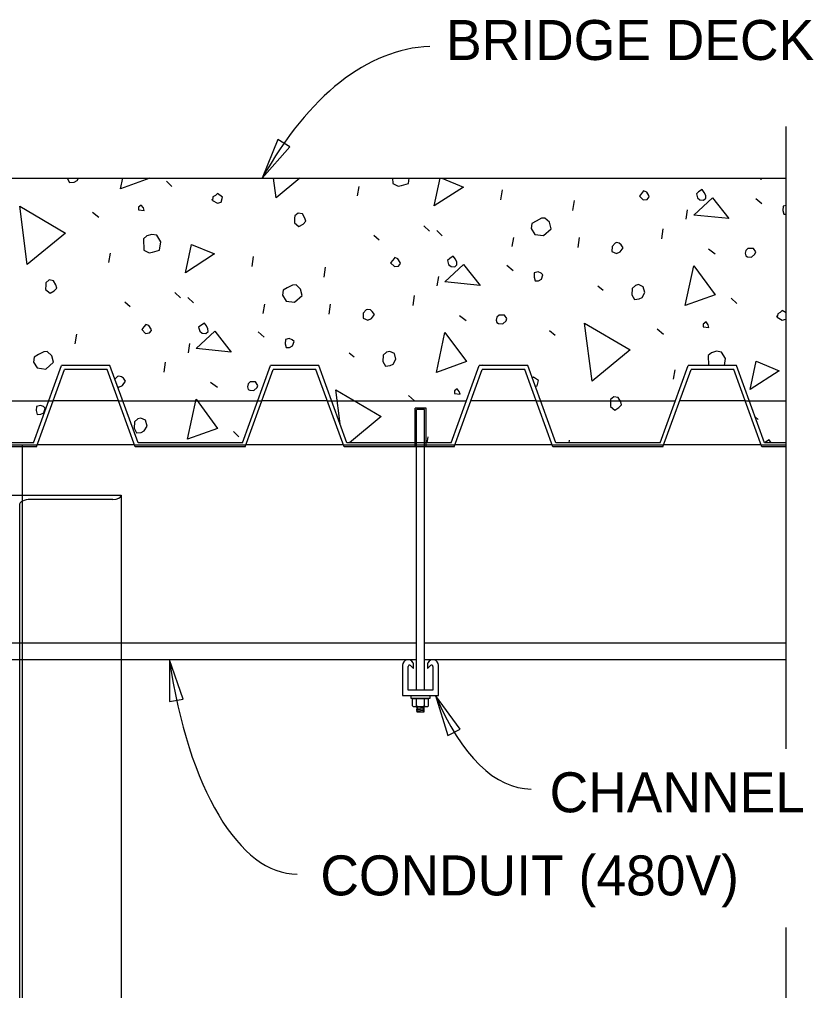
# Model space of a CAD drawing. Extents: x 927736.2 to 927809.6, y 636703.6 to 636757.7.
# Drawn here: x 927796.47 to 927803.88, y 636748.62 to 636757.67 of the extents above; entities that cross this region are included whole.
import ezdxf

# ---------------------------------------------------------------- set-up
doc = ezdxf.new("R2010")
doc.units = 0
for name, color, linetype in [('DimLines_dp', 7, 'Continuous'), ('Miscellaneous1', 7, 'Continuous'), ('Miscellaneous2', 7, 'Continuous'), ('Miscellaneous3', 7, 'Continuous')]:
    doc.layers.add(name, color=color, linetype=linetype)

msp = doc.modelspace()

# ---------------------------------------------------------------- linework, layer by layer
at = {"layer": 'DimLines_dp'}
for points in [[(927803.6221, 636750.8704), (927803.6221, 636756.6765)], [(927803.6221, 636737.7816), (927803.6221, 636747.0555), (927803.431, 636747.0555), (927803.6221, 636747.1387), (927803.8133, 636747.222), (927803.6221, 636747.222), (927803.6221, 636749.2035)]]:
    msp.add_lwpolyline(points, dxfattribs=at)
for points in [[(927798.7324, 636756.1928), (927798.9906, 636756.4861), (927798.8795, 636756.5548)], [(927797.8655, 636751.702), (927797.8657, 636751.3112), (927797.9944, 636751.3331)], [(927800.3508, 636751.368), (927800.4651, 636750.9943), (927800.5818, 636751.0528)]]:
    msp.add_lwpolyline(points, close=True, dxfattribs=at)
for centre, major_axis, ratio, start_param, end_param in [((927800.5703, 636751.583), (0.2741, -5.8397), 0.464296, 3.141604, 3.781059), ((927799.0396, 636752.6162), (0.0188, -2.9139), 0.426092, 5.02876, 6.283138), ((927801.2258, 636753.4099), (0.0188, -2.9139), 0.426092, 5.486066, 6.283138)]:
    msp.add_ellipse(centre, major_axis=major_axis, ratio=ratio, start_param=start_param, end_param=end_param, dxfattribs=at)
at = {"layer": 'Miscellaneous1'}
for p, q in [((927797.4166, 636751.8562), (927795.952, 636751.8562)), ((927800.1719, 636751.8562), (927797.4166, 636751.8562)), ((927803.6221, 636751.8562), (927800.2488, 636751.8562)), ((927797.4166, 636751.702), (927795.952, 636751.702)), ((927800.1719, 636751.702), (927797.4166, 636751.702)), ((927800.146, 636751.6626), (927800.1407, 636751.6733)), ((927800.146, 636751.6185), (927800.146, 636751.6626)), ((927803.6221, 636751.702), (927800.2488, 636751.702)), ((927800.28, 636751.6733), (927800.2747, 636751.6626)), ((927800.2747, 636751.6626), (927800.2747, 636751.6185)), ((927800.0434, 636751.6507), (927800.0434, 636751.368)), ((927800.0947, 636751.4193), (927800.0947, 636751.6388)), ((927800.1166, 636751.6479), (927800.146, 636751.6185)), ((927800.2747, 636751.6185), (927800.3041, 636751.6479)), ((927800.326, 636751.6388), (927800.326, 636751.4193)), ((927800.3773, 636751.368), (927800.3773, 636751.6507)), ((927800.326, 636751.4193), (927800.0947, 636751.4193)), ((927800.0434, 636751.368), (927800.3773, 636751.368))]:
    msp.add_line(p, q, dxfattribs=at)
for centre, radius, start, end in [((927800.0947, 636751.6507), 0.0513, 26.17936, 179.9999), ((927800.326, 636751.6507), 0.0513, 0.0001, 153.82064), ((927800.1075, 636751.6388), 0.0128, 45, 180), ((927800.3132, 636751.6388), 0.0128, 360, 135)]:
    msp.add_arc(centre, radius, start, end, dxfattribs=at)
at = {"layer": 'Miscellaneous2'}
for p, q in [((927786.3327, 636756.1929), (927803.6221, 636756.1929)), ((927803.3889, 636756.1769), (927803.3917, 636756.1929)), ((927797.838, 636756.1643), (927797.8897, 636756.1143)), ((927799.6233, 636756.0298), (927799.6383, 636756.1168)), ((927800.9613, 636755.9924), (927800.9746, 636756.0854)), ((927803.3395, 636756.004), (927803.3971, 636755.9556)), ((927801.6331, 636755.8915), (927801.6465, 636755.9845)), ((927797.1488, 636755.8774), (927797.2064, 636755.829)), ((927802.689, 636755.8106), (927802.704, 636755.8976)), ((927800.2414, 636755.7485), (927800.2931, 636755.6985)), ((927799.7731, 636755.6613), (927799.8232, 636755.6173)), ((927800.3618, 636755.7041), (927800.4135, 636755.6541)), ((927801.0658, 636755.5544), (927801.0808, 636755.6414)), ((927801.6808, 636755.5468), (927801.6942, 636755.6398)), ((927802.4632, 636755.6288), (927802.4766, 636755.7217)), ((927797.3003, 636755.4073), (927797.3153, 636755.4943)), ((927798.6382, 636755.37), (927798.6516, 636755.4629)), ((927802.8971, 636755.5344), (927802.9607, 636755.4876)), ((927801.0164, 636755.3816), (927801.0741, 636755.3332)), ((927799.31, 636755.2691), (927799.3234, 636755.362)), ((927800.366, 636755.1881), (927800.381, 636755.2751)), ((927801.8663, 636755.1879), (927801.9148, 636755.1499)), ((927797.9183, 636755.126), (927797.97, 636755.076)), ((927800.1402, 636755.0063), (927800.1536, 636755.0993)), ((927797.4501, 636755.0388), (927797.5002, 636754.9948)), ((927798.0387, 636755.0817), (927798.0904, 636755.0317)), ((927798.7428, 636754.9319), (927798.7578, 636755.019)), ((927799.3577, 636754.9243), (927799.3711, 636755.0173)), ((927803.1098, 636755.0742), (927803.1615, 636755.0242)), ((927800.5741, 636754.9119), (927800.6377, 636754.8651)), ((927796.987, 636754.6466), (927797.0004, 636754.7396)), ((927798.6934, 636754.7591), (927798.751, 636754.7107)), ((927801.4156, 636754.7735), (927801.4657, 636754.7294)), ((927802.4205, 636754.7874), (927802.4782, 636754.739)), ((927798.0429, 636754.5657), (927798.0579, 636754.6527)), ((927799.5433, 636754.5655), (927799.5918, 636754.5274)), ((927797.8171, 636754.3839), (927797.8305, 636754.4768)), ((927796.5973, 636753.7261), (927796.8593, 636754.4458)), ((927796.6243, 636753.6876), (927796.8862, 636754.4073)), ((927797.3114, 636754.4458), (927796.8593, 636754.4458)), ((927797.2845, 636754.4073), (927796.8862, 636754.4073)), ((927797.5464, 636753.6876), (927797.2845, 636754.4073)), ((927797.5733, 636753.7261), (927797.3114, 636754.4458)), ((927798.5471, 636753.7261), (927798.809, 636754.4458)), ((927798.574, 636753.6876), (927798.836, 636754.4073)), ((927799.2612, 636754.4458), (927798.809, 636754.4458)), ((927799.2342, 636754.4073), (927798.836, 636754.4073)), ((927799.4962, 636753.6876), (927799.2342, 636754.4073)), ((927799.5231, 636753.7261), (927799.2612, 636754.4458)), ((927800.4968, 636753.7261), (927800.7588, 636754.4458)), ((927800.5238, 636753.6876), (927800.7857, 636754.4073)), ((927801.2109, 636754.4458), (927800.7588, 636754.4458)), ((927801.184, 636754.4073), (927800.7857, 636754.4073)), ((927800.7867, 636754.4518), (927800.7929, 636754.4458)), ((927801.4459, 636753.6876), (927801.184, 636754.4073)), ((927801.4728, 636753.7261), (927801.2109, 636754.4458)), ((927802.4466, 636753.7261), (927802.7085, 636754.4458)), ((927802.4735, 636753.6876), (927802.7355, 636754.4073)), ((927802.572, 636754.3173), (927802.587, 636754.4043)), ((927803.1607, 636754.4458), (927802.7085, 636754.4458)), ((927803.1337, 636754.4073), (927802.7355, 636754.4073)), ((927803.3957, 636753.6876), (927803.1337, 636754.4073)), ((927803.4226, 636753.7261), (927803.1607, 636754.4458)), ((927798.251, 636754.2894), (927798.3146, 636754.2426)), ((927800.0975, 636754.1649), (927800.1551, 636754.1165)), ((927800.2617, 636754.0473), (927800.159, 636754.0473)), ((927800.159, 636753.6876), (927800.159, 636754.0473)), ((927800.2488, 636754.0344), (927800.1719, 636754.0344)), ((927800.2617, 636753.6876), (927800.2617, 636754.0473)), ((927803.3344, 636753.9685), (927803.3622, 636753.9416)), ((927798.4637, 636753.8293), (927798.5154, 636753.7793)), ((927800.2715, 636753.7261), (927800.2811, 636753.7818)), ((927801.5968, 636753.7261), (927801.6003, 636753.7504)), ((927796.6243, 636753.6876), (927795.5967, 636753.6876)), ((927796.5973, 636753.7261), (927795.6236, 636753.7261)), ((927798.574, 636753.6876), (927797.5464, 636753.6876)), ((927798.5471, 636753.7261), (927797.5733, 636753.7261)), ((927799.4893, 636753.7065), (927799.6693, 636753.7065)), ((927800.5238, 636753.6876), (927799.4962, 636753.6876)), ((927800.4968, 636753.7261), (927799.5231, 636753.7261)), ((927801.439, 636753.7065), (927801.619, 636753.7065)), ((927802.4735, 636753.6876), (927801.4459, 636753.6876)), ((927802.4466, 636753.7261), (927801.4728, 636753.7261)), ((927803.3888, 636753.7065), (927803.5688, 636753.7065)), ((927803.6221, 636753.6876), (927803.3957, 636753.6876)), ((927803.6221, 636753.7261), (927803.4226, 636753.7261))]:
    msp.add_line(p, q, dxfattribs=at)
for points in [[(927796.912, 636756.1929), (927796.9347, 636756.1521), (927796.978, 636756.1573), (927797.0062, 636756.1712), (927797.0188, 636756.1929)], [(927797.4099, 636756.0942), (927797.4308, 636756.1929)], [(927797.6846, 636756.1929), (927797.4099, 636756.0942)], [(927798.8623, 636756.011), (927798.8392, 636756.1929)], [(927799.083, 636756.1929), (927798.8623, 636756.011)], [(927799.949, 636756.1929), (927799.9505, 636756.143), (927800.0018, 636756.1184), (927800.0316, 636756.1264), (927800.0971, 636756.1439), (927800.1037, 636756.1929)], [(927800.3385, 636755.9341), (927800.3942, 636756.1929)], [(927800.4083, 636756.1929), (927800.6108, 636756.1092), (927800.3385, 636755.9341)], [(927798.2688, 636755.986), (927798.3141, 636755.9599), (927798.3499, 636755.9694), (927798.3625, 636756.0175), (927798.3156, 636756.0496), (927798.295, 636756.0313), (927798.2728, 636756.019), (927798.2688, 636755.986), (927798.2656, 636755.9979)], [(927802.2546, 636756.0262), (927802.2896, 636755.9908), (927802.3269, 636755.9945), (927802.346, 636756.0187), (927802.3428, 636756.0306), (927802.3213, 636756.0632), (927802.2927, 636756.0747), (927802.2736, 636756.0504), (927802.2546, 636756.0262)], [(927802.7617, 636755.8492), (927802.9355, 636756.0107), (927803.0898, 636755.8158), (927802.7617, 636755.8492)], [(927802.7948, 636756.0113), (927802.8191, 636755.9923), (927802.8521, 636755.9883), (927802.8727, 636756.0066), (927802.8723, 636756.0321), (927802.8583, 636756.0602), (927802.8384, 636756.0868), (927802.8059, 636756.0653), (927802.7853, 636756.047), (927802.7948, 636756.0113)], [(927796.5392, 636755.3885), (927796.4702, 636755.9318), (927796.8948, 636755.6817), (927796.5392, 636755.3885)], [(927797.5778, 636755.8966), (927797.6302, 636755.8915), (927797.6238, 636755.9153), (927797.6039, 636755.9419), (927797.5773, 636755.922), (927797.5778, 636755.8966)], [(927803.6221, 636755.9393), (927803.595, 636755.932), (927803.5926, 636755.8931)], [(927799.0345, 636755.8209), (927799.0338, 636755.776), (927799.0747, 636755.7423), (927799.1132, 636755.7654), (927799.1382, 636755.7912), (927799.1302, 636755.821), (927799.1071, 636755.8595), (927799.0666, 636755.8678), (927799.0357, 636755.8404), (927799.0345, 636755.8209)], [(927801.244, 636755.7234), (927801.2778, 636755.6687), (927801.3573, 636755.658), (927801.4295, 636755.7221), (927801.4136, 636755.7816), (927801.371, 636755.8213), (927801.3396, 636755.8193), (927801.2892, 636755.793), (927801.2507, 636755.7699), (927801.244, 636755.7234)], [(927803.5926, 636755.8931), (927803.6022, 636755.8574), (927803.6221, 636755.8586)], [(927797.6242, 636755.6281), (927797.6275, 636755.5205), (927797.6787, 636755.4959), (927797.7085, 636755.5039), (927797.774, 636755.5215), (927797.7847, 636755.6009), (927797.7492, 636755.6617), (927797.7028, 636755.6684), (927797.6551, 636755.6556), (927797.6242, 636755.6281)], [(927798.0154, 636755.3116), (927798.0723, 636755.5759), (927798.2877, 636755.4867), (927798.0154, 636755.3116)], [(927801.9978, 636755.5551), (927801.997, 636755.5102), (927802.0407, 636755.49), (927802.0749, 636755.5056), (927802.1026, 636755.5449), (927802.0827, 636755.5715), (927802.066, 636755.5862), (927802.039, 636755.5917), (927802.0271, 636755.5885), (927801.9978, 636755.5551)], [(927800.4718, 636755.3888), (927800.496, 636755.3698), (927800.529, 636755.3659), (927800.5497, 636755.3842), (927800.5492, 636755.4096), (927800.5353, 636755.4378), (927800.5154, 636755.4644), (927800.4828, 636755.4429), (927800.4622, 636755.4246), (927800.4718, 636755.3888)], [(927803.2467, 636755.4684), (927803.2619, 636755.4597), (927803.3008, 636755.4574), (927803.3317, 636755.4848), (927803.3389, 636755.5059), (927803.3174, 636755.5384), (927803.2665, 636755.5376), (927803.2459, 636755.5193), (927803.2404, 636755.4923), (927803.2467, 636755.4684)], [(927799.9315, 636755.4037), (927799.9665, 636755.3684), (927800.0039, 636755.372), (927800.0229, 636755.3963), (927800.0197, 636755.4082), (927799.9982, 636755.4407), (927799.9696, 636755.4522), (927799.9506, 636755.4279), (927799.9315, 636755.4037)], [(927800.4386, 636755.2267), (927800.6124, 636755.3882), (927800.7668, 636755.1934), (927800.4386, 636755.2267)], [(927802.6816, 636755.0042), (927802.7606, 636755.3765), (927802.9612, 636755.1046), (927802.6816, 636755.0042)], [(927801.2696, 636755.2706), (927801.2791, 636755.2349), (927801.3105, 636755.2369), (927801.3387, 636755.2509), (927801.353, 636755.293), (927801.3363, 636755.3077), (927801.3076, 636755.3191), (927801.2719, 636755.3096), (927801.2696, 636755.2706)], [(927796.7114, 636755.1984), (927796.7107, 636755.1536), (927796.7517, 636755.1198), (927796.7902, 636755.1429), (927796.8152, 636755.1688), (927796.8072, 636755.1986), (927796.7841, 636755.2371), (927796.7436, 636755.2454), (927796.7126, 636755.2179), (927796.7114, 636755.1984)], [(927798.921, 636755.101), (927798.9548, 636755.0462), (927799.0342, 636755.0356), (927799.1065, 636755.0996), (927799.0905, 636755.1592), (927799.0479, 636755.1989), (927799.0166, 636755.1968), (927798.9662, 636755.1706), (927798.9276, 636755.1475), (927798.921, 636755.101)], [(927802.1853, 636755.1649), (927802.1818, 636755.1065), (927802.2065, 636755.062), (927802.2498, 636755.0672), (927802.278, 636755.0812), (927802.3041, 636755.1265), (927802.2898, 636755.1801), (927802.246, 636755.2003), (927802.2163, 636755.1923), (927802.1853, 636755.1649)], [(927799.6747, 636754.9327), (927799.674, 636754.8878), (927799.7177, 636754.8676), (927799.7518, 636754.8831), (927799.7796, 636754.9225), (927799.7597, 636754.9491), (927799.743, 636754.9637), (927799.716, 636754.9693), (927799.7041, 636754.9661), (927799.6747, 636754.9327)], [(927800.9237, 636754.846), (927800.9388, 636754.8373), (927800.9777, 636754.8349), (927801.0087, 636754.8624), (927801.0158, 636754.8834), (927800.9943, 636754.916), (927800.9435, 636754.9151), (927800.9228, 636754.8968), (927800.9173, 636754.8698), (927800.9237, 636754.846)], [(927803.6221, 636754.9358), (927803.5874, 636754.9596), (927803.5668, 636754.9413), (927803.5445, 636754.929), (927803.5406, 636754.896), (927803.5374, 636754.9079)], [(927797.6085, 636754.7812), (927797.6435, 636754.7459), (927797.6808, 636754.7495), (927797.6999, 636754.7738), (927797.6967, 636754.7857), (927797.6752, 636754.8183), (927797.6466, 636754.8297), (927797.6275, 636754.8055), (927797.6085, 636754.7812)], [(927798.1487, 636754.7664), (927798.173, 636754.7473), (927798.206, 636754.7434), (927798.2266, 636754.7617), (927798.2262, 636754.7871), (927798.2122, 636754.8153), (927798.1923, 636754.8419), (927798.1598, 636754.8204), (927798.1392, 636754.8021), (927798.1487, 636754.7664)], [(927801.811, 636754.2985), (927801.742, 636754.8418), (927802.1665, 636754.5916), (927801.811, 636754.2985)], [(927802.8495, 636754.8066), (927802.902, 636754.8015), (927802.8956, 636754.8253), (927802.8757, 636754.8519), (927802.8491, 636754.832), (927802.8495, 636754.8066)], [(927803.5406, 636754.896), (927803.5859, 636754.8698), (927803.6216, 636754.8794), (927803.6221, 636754.8811)], [(927798.1156, 636754.6043), (927798.2894, 636754.7658), (927798.4437, 636754.5709), (927798.1156, 636754.6043)], [(927800.3586, 636754.3817), (927800.4376, 636754.754), (927800.6381, 636754.4822), (927800.3586, 636754.3817)], [(927798.9465, 636754.6482), (927798.9561, 636754.6124), (927798.9875, 636754.6145), (927799.0157, 636754.6284), (927799.0299, 636754.6705), (927799.0132, 636754.6852), (927798.9846, 636754.6967), (927798.9489, 636754.6871), (927798.9465, 636754.6482)], [(927796.5979, 636754.4785), (927796.6317, 636754.4237), (927796.7112, 636754.4131), (927796.7834, 636754.4772), (927796.7674, 636754.5367), (927796.7249, 636754.5764), (927796.6935, 636754.5744), (927796.6431, 636754.5481), (927796.6046, 636754.525), (927796.5979, 636754.4785)], [(927799.8623, 636754.5424), (927799.8588, 636754.484), (927799.8834, 636754.4396), (927799.9267, 636754.4448), (927799.9549, 636754.4587), (927799.9811, 636754.504), (927799.9667, 636754.5576), (927799.923, 636754.5778), (927799.8932, 636754.5699), (927799.8623, 636754.5424)], [(927803.0477, 636754.4458), (927803.0564, 636754.5109), (927803.021, 636754.5716), (927802.9745, 636754.5783), (927802.9269, 636754.5655), (927802.8959, 636754.5381)], [(927802.8959, 636754.5381), (927802.8987, 636754.4458)], [(927803.2872, 636754.2216), (927803.3441, 636754.4858), (927803.5595, 636754.3967), (927803.2872, 636754.2216)], [(927797.3824, 636754.2508), (927797.3946, 636754.2451), (927797.4288, 636754.2606), (927797.4565, 636754.3), (927797.4366, 636754.3266), (927797.4199, 636754.3413), (927797.3929, 636754.3468), (927797.381, 636754.3436), (927797.3581, 636754.3175)], [(927798.6006, 636754.2235), (927798.6157, 636754.2148), (927798.6547, 636754.2125), (927798.6856, 636754.2399), (927798.6928, 636754.261), (927798.6713, 636754.2935), (927798.6204, 636754.2927), (927798.5998, 636754.2744), (927798.5943, 636754.2473), (927798.6006, 636754.2235)], [(927801.2813, 636754.2523), (927801.2986, 636754.2569), (927801.3112, 636754.305), (927801.2643, 636754.3371), (927801.2538, 636754.3278)], [(927799.4593, 636753.9014), (927799.4189, 636754.2193), (927799.8435, 636753.9692), (927799.5487, 636753.7261)], [(927800.5265, 636754.1841), (927800.5789, 636754.179), (927800.5725, 636754.2028), (927800.5526, 636754.2294), (927800.526, 636754.2095), (927800.5265, 636754.1841)], [(927798.0355, 636753.7593), (927798.1145, 636754.1316), (927798.3151, 636753.8597), (927798.0355, 636753.7593)], [(927801.9832, 636754.1084), (927801.9825, 636754.0635), (927802.0234, 636754.0298), (927802.0619, 636754.0529), (927802.0869, 636754.0787), (927802.0789, 636754.1085), (927802.0558, 636754.147), (927802.0153, 636754.1553), (927801.9844, 636754.1279), (927801.9832, 636754.1084)], [(927796.6235, 636754.0257), (927796.633, 636753.99), (927796.6644, 636753.992), (927796.6926, 636754.0059), (927796.7069, 636754.0481), (927796.6902, 636754.0627), (927796.6615, 636754.0742), (927796.6258, 636754.0646), (927796.6235, 636754.0257)], [(927797.5392, 636753.92), (927797.5357, 636753.8616), (927797.5604, 636753.8171), (927797.6037, 636753.8223), (927797.6319, 636753.8363), (927797.658, 636753.8816), (927797.6437, 636753.9352), (927797.5999, 636753.9554), (927797.5702, 636753.9474), (927797.5392, 636753.92)], [(927803.4834, 636753.7261), (927803.4641, 636753.7519), (927803.4316, 636753.7304), (927803.4267, 636753.7261)]]:
    msp.add_lwpolyline(points, dxfattribs=at)
at = {"layer": 'Miscellaneous3'}
for p, q in [((927795.4401, 636754.1177), (927796.7808, 636754.1177)), ((927797.3899, 636754.1177), (927796.7808, 636754.1177)), ((927797.3899, 636754.1177), (927798.7306, 636754.1177)), ((927799.3396, 636754.1177), (927798.7306, 636754.1177)), ((927799.3396, 636754.1177), (927800.6394, 636754.1177)), ((927801.2894, 636754.1177), (927800.6803, 636754.1177)), ((927801.2894, 636754.1177), (927802.5891, 636754.1177)), ((927803.2391, 636754.1177), (927802.6301, 636754.1177)), ((927803.2391, 636754.1177), (927803.6221, 636754.1177)), ((927800.1719, 636751.4193), (927800.1719, 636754.0344)), ((927800.2488, 636751.4193), (927800.2488, 636754.0344)), ((927795.5898, 636753.7065), (927796.6311, 636753.7065)), ((927796.4917, 636753.7065), (927796.4917, 636753.2366)), ((927797.5396, 636753.7065), (927796.6311, 636753.7065)), ((927797.5395, 636753.7065), (927798.5809, 636753.7065)), ((927799.4893, 636753.7065), (927798.5809, 636753.7065)), ((927799.4893, 636753.7065), (927800.5306, 636753.7065)), ((927801.4391, 636753.7065), (927800.5306, 636753.7065)), ((927801.439, 636753.7065), (927802.4804, 636753.7065)), ((927803.3888, 636753.7065), (927802.4804, 636753.7065)), ((927803.3888, 636753.7065), (927803.6221, 636753.7065)), ((927796.3888, 636753.2366), (927797.4166, 636753.2366)), ((927796.4917, 636753.2366), (927796.4917, 636741.1643)), ((927797.3395, 636753.1967), (927796.5687, 636753.1967)), ((927797.4166, 636753.2366), (927797.4166, 636741.2221)), ((927796.4659, 636753.1435), (927796.4659, 636752.7445)), ((927796.4659, 636752.7445), (927796.4659, 636740.7295)), ((927800.1361, 636751.2706), (927800.1361, 636751.3406)), ((927800.1361, 636751.3406), (927800.2845, 636751.3406)), ((927800.1732, 636751.2706), (927800.1732, 636751.3406)), ((927800.2474, 636751.2706), (927800.2474, 636751.3406)), ((927800.2845, 636751.2706), (927800.2845, 636751.3406)), ((927800.1546, 636751.2651), (927800.2659, 636751.2651)), ((927800.1717, 636751.2637), (927800.188, 636751.2651)), ((927800.1717, 636751.2637), (927800.1743, 636751.2651)), ((927800.1847, 636751.2583), (927800.1717, 636751.2637)), ((927800.1717, 636751.2508), (927800.1847, 636751.2583)), ((927800.1717, 636751.2508), (927800.2488, 636751.2575)), ((927800.1847, 636751.2454), (927800.1717, 636751.2508)), ((927800.1717, 636751.2381), (927800.1847, 636751.2454)), ((927800.1717, 636751.2381), (927800.2488, 636751.2446)), ((927800.1847, 636751.2327), (927800.1717, 636751.2381)), ((927800.1717, 636751.2252), (927800.1847, 636751.2327)), ((927800.1717, 636751.2252), (927800.2488, 636751.2319)), ((927800.1847, 636751.2198), (927800.1717, 636751.2252)), ((927800.1762, 636751.2151), (927800.1847, 636751.2198)), ((927800.1762, 636751.2151), (927800.2417, 636751.2151)), ((927800.2011, 636751.2151), (927800.2488, 636751.2191)), ((927800.2358, 636751.2628), (927800.2398, 636751.2651)), ((927800.2488, 636751.2575), (927800.2358, 636751.2628)), ((927800.2358, 636751.2499), (927800.2488, 636751.2575)), ((927800.2488, 636751.2446), (927800.2358, 636751.2499)), ((927800.2358, 636751.2372), (927800.2488, 636751.2446)), ((927800.2488, 636751.2319), (927800.2358, 636751.2372)), ((927800.2358, 636751.2243), (927800.2488, 636751.2319)), ((927800.2488, 636751.2191), (927800.2358, 636751.2243)), ((927800.2417, 636751.2151), (927800.2488, 636751.2191))]:
    msp.add_line(p, q, dxfattribs=at)
msp.add_lwpolyline([(927800.2973, 636751.368), (927800.2973, 636751.3406), (927800.1233, 636751.3406), (927800.1233, 636751.368)], close=True, dxfattribs=at)
for centre, radius, start, end in [((927800.1546, 636751.2991), 0.034, 236.97907, 303.02093), ((927800.2103, 636751.393), 0.1279, 253.13957, 286.86043), ((927800.2659, 636751.2991), 0.034, 236.97907, 303.02093)]:
    msp.add_arc(centre, radius, start, end, dxfattribs=at)
for centre, major_axis in [((927796.5687, 636753.1435), (-0.1028, 0)), ((927797.3395, 636753.2366), (0.0771, 0))]:
    msp.add_ellipse(centre, major_axis=major_axis, ratio=0.5176, start_param=4.712389, end_param=6.283185, dxfattribs=at)

# ---------------------------------------------------------------- texts
at = {"layer": 'DimLines_dp'}
for s, height, p in [('BRIDGE DECK', 0.372961, (927800.4488, 636757.2953)), ('CHANNEL', 0.37296, (927801.4153, 636750.2787)), ('CONDUIT (480V)', 0.372961, (927799.2752, 636749.5037))]:
    msp.add_text(s, height=height, dxfattribs=at).set_placement(p)

doc.saveas('drawing.dxf')
